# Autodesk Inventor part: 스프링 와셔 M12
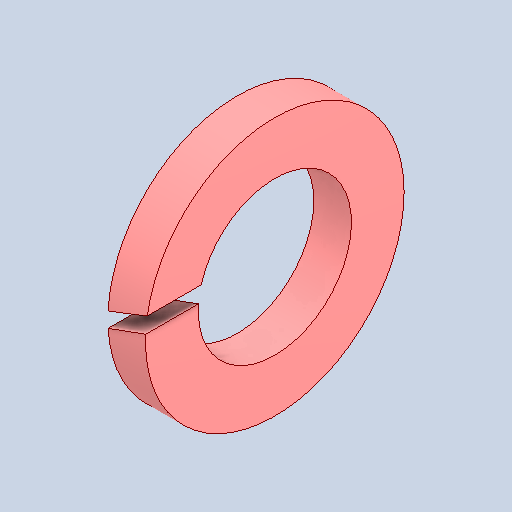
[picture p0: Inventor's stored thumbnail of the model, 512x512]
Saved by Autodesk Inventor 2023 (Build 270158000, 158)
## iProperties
Created: 2025-03
Part Number: 스프링 와셔 M12
Material: 강철, 연강
Description: 스프링 잠금 와셔
Document SubType Name: Modeling
Designer: User
Density: 7.85 g/cm^3
Appearance: 기본값
Author: jhkim
Sending System: Autodesk Inventor 2025
Preprocessor: ST-DEVELOPER v20
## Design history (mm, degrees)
feature "Solid1"
node "솔리드1"
